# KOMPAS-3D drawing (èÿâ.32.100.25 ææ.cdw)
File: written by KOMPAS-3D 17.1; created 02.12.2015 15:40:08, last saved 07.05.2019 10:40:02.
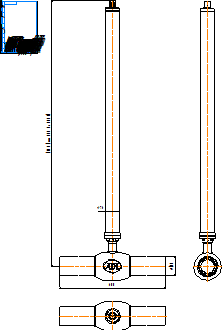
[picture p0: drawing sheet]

Sheet 1: A4, portrait

Title block, sheet 1: name: КШГ.32.100.25 СС; material: Внимание! Данный продукт является объектом авторского права ООО «Торговый Дом АДЛ». / Запрещается изменение, копирование, распространение / (в том числе путем копирования на другие сайты и ресурсы в Интернете) / или любое иное использование информации и объектов без предварительного / согласия правообладателя (ООО «Торговый Дом АДЛ»).; sheets: 1; organisation: ООО "Торговый дом АДЛ"; sheet format: A4; stored path: C:\Users\kka\KOMPAS_Work\Модели кранов для исследований\DN50\С удлинением\КШГ.32.050.40 СС ГЧ _ Шаровой кран БИВАЛ Ду50 Ру4 МПа редуцированный под приварку, с удлинением штока H=1100.cdw; drawn by: Климкович К.А.; drawn by, date: 02.12.15

Views: Вид 1, Проекционный вид 2, Проекционный вид 3
Referenced files in C:\Users\kka\KOMPAS_Work\Модели кранов для исследований\DN80\С удлинением\: КШТ.22.080.25 СС.a3d, КШГ.35.065.25 СС.a3d!КШГ.45.065.10 СС!Деталь (локальная).m3d
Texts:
  Klimkovich
  ADL
  (от 380 до 5000)
Dimensions and other numbers on the sheet: 600; 1500; 108; 76; 1:1; 1; 02.12.15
